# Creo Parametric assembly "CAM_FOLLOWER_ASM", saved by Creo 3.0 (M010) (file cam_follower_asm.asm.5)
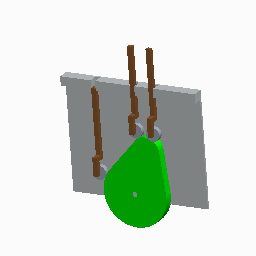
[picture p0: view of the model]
Units: Inch lbm Second (Pro/E Default); INCH, POUND, SECS

Created from: INLBS_ASM_DESIGN.ASM

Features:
  1. datum plane "ASM_RIGHT"
  2. datum plane "ASM_TOP"
  3. datum plane "ASM_FRONT"
  4. coordinate system
  5. component "BASE"
  6. component "FOLLOWER_BAR"
  7. component "FOLLOWER_ROLLER"
  8. component "FOLLOWER_ASM", "ASM0001.ASM"
  9. component "FOLLOWER_ASM", "ASM0001.ASM"
  10. component "CAM"

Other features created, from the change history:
  component "CAM001.PRT"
